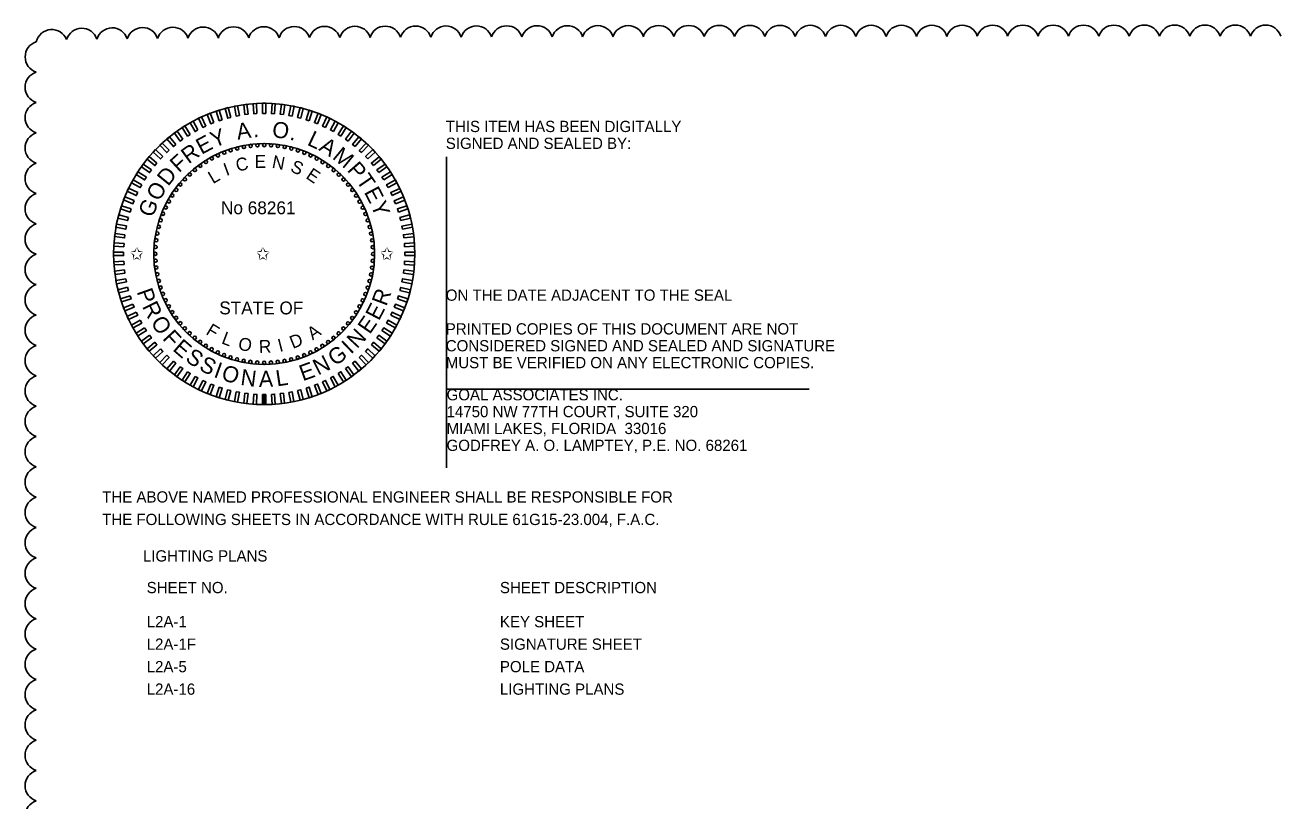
# Model space of a CAD drawing. Extents: x -811 to -790, y -2284 to -2178.
# Drawn here: x -810.98 to -803.16, y -2265.38 to -2260.55 of the extents above; entities that cross this region are included whole.
import ezdxf

# ---------------------------------------------------------------- set-up
doc = ezdxf.new("R2010")
doc.units = 0
for name, color, linetype in [('AdhocPoint_dp', 7, 'Continuous'), ('PlotBorder_dp', 7, 'Continuous'), ('ScratchEle_dp', 7, 'Continuous'), ('TextMinor', 7, 'Continuous'), ('TextMisc', 7, 'Continuous'), ('TextShtNo', 7, 'Continuous')]:
    doc.layers.add(name, color=color, linetype=linetype)

msp = doc.modelspace()

# ---------------------------------------------------------------- linework, layer by layer
at = {"layer": 'AdhocPoint_dp'}
for p, q in [((-808.3546, -2261.3703), (-808.3546, -2263.305)), ((-808.3546, -2262.815), (-806.0979, -2262.815))]:
    msp.add_line(p, q, dxfattribs=at)
at = {"layer": 'ScratchEle_dp'}
for centre, radius, start, end in [((-809.1139, -2260.6566), 0.0991, 17.73544, 162.73544), ((-808.9249, -2260.6558), 0.0991, 17.7132, 162.7132), ((-808.736, -2260.6551), 0.0991, 17.69393, 162.69393), ((-808.547, -2260.6545), 0.0991, 17.67702, 162.67702), ((-808.358, -2260.654), 0.0991, 17.66204, 162.66204), ((-808.169, -2260.6535), 0.0991, 17.64863, 162.64863), ((-807.98, -2260.653), 0.0991, 17.63655, 162.63655), ((-807.791, -2260.6526), 0.0991, 17.62558, 162.62558), ((-807.602, -2260.6522), 0.0991, 17.61556, 162.61556), ((-807.413, -2260.6518), 0.0991, 17.60637, 162.60637), ((-807.224, -2260.6515), 0.0991, 17.5979, 162.5979), ((-807.035, -2260.6512), 0.0991, 17.59006, 162.59006), ((-806.846, -2260.6509), 0.0991, 17.58277, 162.58277), ((-806.657, -2260.6506), 0.0991, 17.57597, 162.57597), ((-806.468, -2260.6504), 0.0991, 17.56961, 162.56961), ((-806.279, -2260.6501), 0.0991, 17.56364, 162.56364), ((-806.09, -2260.6499), 0.0991, 17.55803, 162.55803), ((-805.901, -2260.6498), 0.0991, 17.55274, 162.55274), ((-805.712, -2260.6496), 0.0991, 17.54774, 162.54774), ((-805.523, -2260.6494), 0.0991, 17.54301, 162.54301), ((-805.334, -2260.6493), 0.0991, 17.53852, 162.53852), ((-805.145, -2260.6492), 0.0991, 17.53425, 162.53425), ((-804.956, -2260.6491), 0.0991, 17.53018, 162.53018), ((-804.767, -2260.649), 0.0991, 17.52631, 162.52631), ((-804.578, -2260.6489), 0.0991, 17.52261, 162.52261), ((-804.389, -2260.6488), 0.0991, 17.51907, 162.51907), ((-804.2, -2260.6488), 0.0991, 17.51569, 162.51569), ((-804.011, -2260.6487), 0.0991, 17.51244, 162.51244), ((-803.822, -2260.6487), 0.0991, 17.50933, 162.50933), ((-803.633, -2260.6487), 0.0991, 17.50633, 162.50633), ((-803.444, -2260.6487), 0.0991, 17.50345, 162.50345), ((-803.2551, -2260.6487), 0.0991, 17.50077, 162.50077), ((-810.8128, -2260.6762), 0.0992, 21.52097, 166.52097), ((-810.6255, -2260.6681), 0.0991, 18.44241, 163.44241), ((-810.4367, -2260.6654), 0.0991, 18.17187, 163.17187), ((-810.2478, -2260.6635), 0.0991, 18.03188, 163.03188), ((-810.0588, -2260.6618), 0.0991, 17.94243, 162.94243), ((-809.8699, -2260.6605), 0.0991, 17.8789, 162.8789), ((-809.6809, -2260.6593), 0.0991, 17.83076, 162.83076), ((-809.4919, -2260.6583), 0.0991, 17.79266, 162.79266), ((-809.3029, -2260.6574), 0.0991, 17.76151, 162.76151), ((-810.8794, -2260.7476), 0.099, 107.5, 252.5), ((-810.8794, -2260.9365), 0.0991, 107.5, 252.5), ((-810.8794, -2261.1255), 0.0991, 107.5, 252.5), ((-810.8794, -2261.3145), 0.0991, 107.5, 252.5), ((-810.8794, -2261.5035), 0.0991, 107.5, 252.5), ((-810.8794, -2261.6925), 0.0991, 107.5, 252.5), ((-810.8794, -2261.8815), 0.0991, 107.5, 252.5), ((-810.8794, -2262.0705), 0.0991, 107.5, 252.5), ((-810.8794, -2262.2595), 0.0991, 107.5, 252.5), ((-810.8794, -2262.4485), 0.0991, 107.5, 252.5), ((-810.8794, -2262.6375), 0.0991, 107.5, 252.5), ((-810.8794, -2262.8265), 0.0991, 107.5, 252.5), ((-810.8794, -2263.0155), 0.0991, 107.5, 252.5), ((-810.8794, -2263.2045), 0.0991, 107.5, 252.5), ((-810.8794, -2263.3935), 0.0991, 107.5, 252.5), ((-810.8794, -2263.5825), 0.0991, 107.5, 252.5), ((-810.8794, -2263.7715), 0.0991, 107.5, 252.5), ((-810.8794, -2263.9605), 0.0991, 107.5, 252.5), ((-810.8794, -2264.1495), 0.0991, 107.5, 252.5), ((-810.8794, -2264.3385), 0.0991, 107.5, 252.5), ((-810.8794, -2264.5275), 0.0991, 107.5, 252.5), ((-810.8794, -2264.7165), 0.0991, 107.5, 252.5), ((-810.8794, -2264.9055), 0.0991, 107.5, 252.5), ((-810.8794, -2265.0945), 0.0991, 107.5, 252.5), ((-810.8794, -2265.2835), 0.0991, 107.50047, 252.50047), ((-810.8794, -2265.4725), 0.0991, 107.52584, 252.52584)]:
    msp.add_arc(centre, radius, start, end, dxfattribs=at)
at = {"layer": 'TextMinor'}
for radius in [0.9375, 0.6875]:
    msp.add_circle((-809.4901, -2261.9737), radius, dxfattribs=at)
at = {"layer": 'TextShtNo'}
for p, q in [((-809.5001, -2262.9113), (-809.5003, -2262.8488)), ((-809.4901, -2262.9112), (-809.4903, -2262.8487)), ((-809.4801, -2262.9112), (-809.4803, -2262.8487))]:
    msp.add_line(p, q, dxfattribs=at)
for points in [[(-809.8028, -2261.1564), (-809.8215, -2261.1638), (-809.8445, -2261.1058), (-809.8258, -2261.0983)], [(-809.7508, -2261.1384), (-809.77, -2261.1446), (-809.7893, -2261.0852), (-809.7701, -2261.079)], [(-809.6979, -2261.1237), (-809.7174, -2261.1287), (-809.7329, -2261.0682), (-809.7134, -2261.0632)], [(-809.6441, -2261.1123), (-809.6639, -2261.1161), (-809.6756, -2261.0547), (-809.6558, -2261.051)], [(-809.5897, -2261.1043), (-809.6097, -2261.1069), (-809.6175, -2261.0449), (-809.5975, -2261.0424)], [(-809.5349, -2261.0998), (-809.555, -2261.1011), (-809.559, -2261.0387), (-809.5388, -2261.0375)], [(-809.4799, -2261.0987), (-809.5001, -2261.0987), (-809.5001, -2261.0363), (-809.4799, -2261.0363)], [(-809.425, -2261.1011), (-809.4452, -2261.0998), (-809.4412, -2261.0375), (-809.4211, -2261.0387)], [(-809.3703, -2261.1069), (-809.3904, -2261.1043), (-809.3825, -2261.0424), (-809.3625, -2261.0449)], [(-809.3161, -2261.1161), (-809.336, -2261.1123), (-809.3243, -2261.051), (-809.3044, -2261.0548)], [(-809.2626, -2261.1287), (-809.2822, -2261.1237), (-809.2667, -2261.0632), (-809.2471, -2261.0682)], [(-809.21, -2261.1447), (-809.2292, -2261.1384), (-809.2099, -2261.0791), (-809.1907, -2261.0853)], [(-809.1585, -2261.1639), (-809.1773, -2261.1565), (-809.1543, -2261.0984), (-809.1355, -2261.1058)], [(-809.9504, -2261.2295), (-809.9674, -2261.2403), (-810.0009, -2261.1876), (-809.9838, -2261.1767)], [(-809.9027, -2261.202), (-809.9204, -2261.2118), (-809.9505, -2261.157), (-809.9328, -2261.1473)], [(-809.8535, -2261.1776), (-809.8717, -2261.1862), (-809.8983, -2261.1297), (-809.8801, -2261.1211)], [(-809.1083, -2261.1863), (-809.1266, -2261.1777), (-809.1, -2261.1212), (-809.0817, -2261.1298)], [(-809.0596, -2261.2118), (-809.0773, -2261.2021), (-809.0473, -2261.1474), (-809.0296, -2261.1571)], [(-809.0127, -2261.2404), (-809.0297, -2261.2296), (-808.9962, -2261.1768), (-808.9792, -2261.1877)], [(-810.04, -2261.293), (-810.0556, -2261.3059), (-810.0954, -2261.2578), (-810.0798, -2261.2449)], [(-809.9962, -2261.2598), (-810.0125, -2261.2717), (-810.0492, -2261.2212), (-810.0329, -2261.2093)], [(-808.9675, -2261.2718), (-808.9839, -2261.2599), (-808.9472, -2261.2094), (-808.9308, -2261.2213)], [(-808.9245, -2261.306), (-808.9401, -2261.2931), (-808.9003, -2261.245), (-808.8847, -2261.2579)], [(-810.121, -2261.3673), (-810.1348, -2261.382), (-810.1803, -2261.3393), (-810.1665, -2261.3246)], [(-810.0817, -2261.3289), (-810.0964, -2261.3427), (-810.1391, -2261.2972), (-810.1244, -2261.2834)], [(-808.8837, -2261.3428), (-808.8984, -2261.329), (-808.8557, -2261.2835), (-808.8409, -2261.2973)], [(-808.8453, -2261.3822), (-808.8591, -2261.3674), (-808.8136, -2261.3247), (-808.7998, -2261.3394)], [(-810.192, -2261.4512), (-810.2039, -2261.4675), (-810.2544, -2261.4308), (-810.2426, -2261.4145)], [(-810.1578, -2261.4081), (-810.1707, -2261.4237), (-810.2188, -2261.3839), (-810.206, -2261.3683)], [(-808.8094, -2261.4238), (-808.8223, -2261.4083), (-808.7742, -2261.3685), (-808.7613, -2261.384)], [(-808.7762, -2261.4676), (-808.7881, -2261.4513), (-808.7376, -2261.4146), (-808.7257, -2261.4309)], [(-810.2235, -2261.4963), (-810.2343, -2261.5133), (-810.287, -2261.4798), (-810.2762, -2261.4628)], [(-808.7458, -2261.5135), (-808.7567, -2261.4964), (-808.7039, -2261.463), (-808.6931, -2261.48)], [(-810.2775, -2261.5919), (-810.2861, -2261.6102), (-810.3426, -2261.5836), (-810.334, -2261.5654)], [(-810.252, -2261.5433), (-810.2617, -2261.5609), (-810.3164, -2261.5309), (-810.3067, -2261.5132)], [(-808.7184, -2261.5611), (-808.7281, -2261.5434), (-808.6734, -2261.5133), (-808.6637, -2261.531)], [(-808.694, -2261.6104), (-808.7026, -2261.5921), (-808.6461, -2261.5655), (-808.6375, -2261.5838)], [(-810.3, -2261.6421), (-810.3074, -2261.6609), (-810.3654, -2261.6379), (-810.358, -2261.6192)], [(-808.6728, -2261.6611), (-808.6802, -2261.6423), (-808.6222, -2261.6193), (-808.6147, -2261.6381)], [(-810.3351, -2261.7463), (-810.3401, -2261.7658), (-810.4006, -2261.7503), (-810.3956, -2261.7307)], [(-810.3192, -2261.6936), (-810.3254, -2261.7128), (-810.3848, -2261.6935), (-810.3786, -2261.6743)], [(-808.6548, -2261.713), (-808.661, -2261.6938), (-808.6016, -2261.6745), (-808.5954, -2261.6937)], [(-808.64, -2261.766), (-808.6451, -2261.7464), (-808.5846, -2261.7309), (-808.5796, -2261.7505)], [(-810.3477, -2261.7998), (-810.3515, -2261.8196), (-810.4129, -2261.8079), (-810.4091, -2261.7881)], [(-808.6287, -2261.8198), (-808.6325, -2261.7999), (-808.5711, -2261.7882), (-808.5673, -2261.8081)], [(-810.357, -2261.854), (-810.3595, -2261.874), (-810.4214, -2261.8662), (-810.4189, -2261.8461)], [(-808.6207, -2261.8742), (-808.6232, -2261.8541), (-808.5613, -2261.8463), (-808.5588, -2261.8663)], [(-810.3651, -2261.9635), (-810.3651, -2261.9837), (-810.4276, -2261.9837), (-810.4276, -2261.9635)], [(-810.3628, -2261.9086), (-810.364, -2261.9288), (-810.4264, -2261.9248), (-810.4251, -2261.9047)], [(-808.6162, -2261.929), (-808.6174, -2261.9088), (-808.5551, -2261.9049), (-808.5539, -2261.925)], [(-808.6151, -2261.9839), (-808.6151, -2261.9637), (-808.5526, -2261.9637), (-808.5526, -2261.9839)], [(-810.3641, -2262.0185), (-810.3628, -2262.0387), (-810.4251, -2262.0426), (-810.4264, -2262.0224)], [(-808.6175, -2262.0388), (-808.6162, -2262.0187), (-808.5539, -2262.0226), (-808.5551, -2262.0428)], [(-810.3595, -2262.0733), (-810.357, -2262.0933), (-810.4189, -2262.1011), (-810.4215, -2262.0811)], [(-808.6233, -2262.0935), (-808.6207, -2262.0735), (-808.5588, -2262.0813), (-808.5613, -2262.1013)], [(-810.3516, -2262.1277), (-810.3478, -2262.1475), (-810.4091, -2262.1592), (-810.4129, -2262.1394)], [(-810.3402, -2262.1815), (-810.3352, -2262.201), (-810.3956, -2262.2166), (-810.4007, -2262.197)], [(-808.6451, -2262.2012), (-808.6401, -2262.1817), (-808.5796, -2262.1972), (-808.5846, -2262.2167)], [(-808.6325, -2262.1477), (-808.6287, -2262.1279), (-808.5674, -2262.1396), (-808.5712, -2262.1594)], [(-810.3255, -2262.2344), (-810.3192, -2262.2536), (-810.3786, -2262.2729), (-810.3849, -2262.2537)], [(-808.6611, -2262.2538), (-808.6548, -2262.2346), (-808.5954, -2262.2539), (-808.6017, -2262.2731)], [(-810.3074, -2262.2864), (-810.3, -2262.3051), (-810.3581, -2262.3281), (-810.3655, -2262.3094)], [(-810.2862, -2262.3371), (-810.2776, -2262.3553), (-810.3341, -2262.3819), (-810.3427, -2262.3637)], [(-808.7027, -2262.3555), (-808.6941, -2262.3372), (-808.6376, -2262.3638), (-808.6462, -2262.3821)], [(-808.6803, -2262.3053), (-808.6729, -2262.2866), (-808.6148, -2262.3095), (-808.6222, -2262.3283)], [(-810.2618, -2262.3864), (-810.2521, -2262.404), (-810.3068, -2262.4341), (-810.3165, -2262.4164)], [(-810.2344, -2262.434), (-810.2236, -2262.451), (-810.2763, -2262.4845), (-810.2871, -2262.4674)], [(-808.7568, -2262.4512), (-808.7459, -2262.4341), (-808.6932, -2262.4676), (-808.704, -2262.4847)], [(-808.7282, -2262.4042), (-808.7185, -2262.3865), (-808.6638, -2262.4166), (-808.6735, -2262.4343)], [(-810.204, -2262.4798), (-810.1922, -2262.4961), (-810.2427, -2262.5328), (-810.2545, -2262.5165)], [(-808.7882, -2262.4963), (-808.7763, -2262.48), (-808.7258, -2262.5167), (-808.7377, -2262.533)], [(-810.1708, -2262.5236), (-810.158, -2262.5392), (-810.2061, -2262.579), (-810.2189, -2262.5634)], [(-810.135, -2262.5653), (-810.1211, -2262.58), (-810.1667, -2262.6228), (-810.1805, -2262.608)], [(-808.8592, -2262.5802), (-808.8454, -2262.5654), (-808.7999, -2262.6082), (-808.8137, -2262.6229)], [(-808.8224, -2262.5393), (-808.8095, -2262.5238), (-808.7614, -2262.5636), (-808.7743, -2262.5791)], [(-810.0965, -2262.6046), (-810.0818, -2262.6184), (-810.1246, -2262.664), (-810.1393, -2262.6501)], [(-810.0557, -2262.6415), (-810.0402, -2262.6543), (-810.08, -2262.7024), (-810.0955, -2262.6896)], [(-808.9402, -2262.6544), (-808.9246, -2262.6416), (-808.8848, -2262.6897), (-808.9004, -2262.7026)], [(-808.8985, -2262.6186), (-808.8838, -2262.6048), (-808.8411, -2262.6503), (-808.8558, -2262.6641)], [(-810.0127, -2262.6757), (-809.9964, -2262.6875), (-810.0331, -2262.738), (-810.0494, -2262.7262)], [(-809.9676, -2262.7071), (-809.9505, -2262.7179), (-809.984, -2262.7706), (-810.001, -2262.7598)], [(-809.9206, -2262.7356), (-809.9029, -2262.7453), (-809.933, -2262.8001), (-809.9507, -2262.7903)], [(-809.0775, -2262.7454), (-809.0598, -2262.7357), (-809.0297, -2262.7904), (-809.0474, -2262.8001)], [(-809.0299, -2262.718), (-809.0128, -2262.7072), (-808.9794, -2262.7599), (-808.9964, -2262.7707)], [(-808.984, -2262.6876), (-808.9677, -2262.6758), (-808.931, -2262.7263), (-808.9473, -2262.7381)], [(-809.8719, -2262.7611), (-809.8536, -2262.7697), (-809.8802, -2262.8262), (-809.8985, -2262.8176)], [(-809.8217, -2262.7836), (-809.8029, -2262.791), (-809.8259, -2262.849), (-809.8447, -2262.8416)], [(-809.7702, -2262.8028), (-809.751, -2262.809), (-809.7703, -2262.8684), (-809.7895, -2262.8622)], [(-809.7176, -2262.8187), (-809.698, -2262.8238), (-809.7136, -2262.8842), (-809.7331, -2262.8792)], [(-809.2824, -2262.8238), (-809.2628, -2262.8188), (-809.2473, -2262.8793), (-809.2668, -2262.8843)], [(-809.2294, -2262.8091), (-809.2102, -2262.8028), (-809.1909, -2262.8622), (-809.2101, -2262.8685)], [(-809.1775, -2262.7911), (-809.1587, -2262.7836), (-809.1357, -2262.8417), (-809.1545, -2262.8491)], [(-809.1268, -2262.7698), (-809.1085, -2262.7612), (-809.0819, -2262.8177), (-809.1002, -2262.8263)], [(-809.6641, -2262.8314), (-809.6443, -2262.8351), (-809.656, -2262.8965), (-809.6758, -2262.8927)], [(-809.6099, -2262.8406), (-809.5899, -2262.8431), (-809.5977, -2262.9051), (-809.6177, -2262.9025)], [(-809.5552, -2262.8464), (-809.5351, -2262.8477), (-809.539, -2262.91), (-809.5591, -2262.9087)], [(-809.5003, -2262.8488), (-809.4801, -2262.8488), (-809.4801, -2262.9112), (-809.5003, -2262.9112)], [(-809.4453, -2262.8477), (-809.4252, -2262.8464), (-809.4213, -2262.9087), (-809.4414, -2262.91)], [(-809.3906, -2262.8431), (-809.3705, -2262.8406), (-809.3627, -2262.9026), (-809.3827, -2262.9051)], [(-809.3362, -2262.8352), (-809.3163, -2262.8314), (-809.3046, -2262.8927), (-809.3245, -2262.8965)]]:
    msp.add_lwpolyline(points, close=True, dxfattribs=at)
for centre in [(-809.739, -2261.3436), (-809.6989, -2261.3292), (-809.6581, -2261.3174), (-809.6165, -2261.3082), (-809.5745, -2261.3015), (-809.5321, -2261.2976), (-809.4896, -2261.2963), (-809.447, -2261.2976), (-809.4046, -2261.3017), (-809.3626, -2261.3084), (-809.3211, -2261.3177), (-809.2802, -2261.3296), (-809.2402, -2261.344), (-809.8879, -2261.4253), (-809.8526, -2261.4014), (-809.816, -2261.3798), (-809.7781, -2261.3605), (-809.2012, -2261.361), (-809.1633, -2261.3803), (-809.1266, -2261.402), (-809.0915, -2261.426), (-809.9535, -2261.4795), (-809.9215, -2261.4514), (-809.0578, -2261.4521), (-809.0259, -2261.4803), (-810.0379, -2261.5751), (-810.0118, -2261.5415), (-809.9836, -2261.5096), (-808.9959, -2261.5104), (-808.9678, -2261.5423), (-808.9417, -2261.576), (-810.0835, -2261.6469), (-810.0618, -2261.6102), (-808.9178, -2261.6112), (-808.8962, -2261.6478), (-810.1198, -2261.7238), (-810.1029, -2261.6848), (-808.8769, -2261.6858), (-808.86, -2261.7249), (-810.1462, -2261.8047), (-810.1343, -2261.7638), (-808.8456, -2261.7649), (-808.8338, -2261.8058), (-810.1622, -2261.8883), (-810.1555, -2261.8462), (-808.8245, -2261.8473), (-808.8179, -2261.8894), (-810.1676, -2261.9732), (-810.1662, -2261.9306), (-808.814, -2261.9318), (-808.8126, -2261.9743), (-810.1663, -2262.0157), (-808.814, -2262.0168), (-810.1623, -2262.0581), (-810.1557, -2262.1001), (-808.8248, -2262.1012), (-808.8181, -2262.0592), (-810.1464, -2262.1417), (-810.1346, -2262.1825), (-808.846, -2262.1836), (-808.8341, -2262.1428), (-810.1202, -2262.2226), (-810.1033, -2262.2617), (-808.8774, -2262.2627), (-808.8604, -2262.2236), (-810.0841, -2262.2996), (-810.0624, -2262.3363), (-808.9184, -2262.3372), (-808.8967, -2262.3006), (-810.0385, -2262.3715), (-810.0125, -2262.4051), (-809.9844, -2262.4371), (-808.9967, -2262.4379), (-808.9685, -2262.406), (-808.9424, -2262.3724), (-809.9543, -2262.4672), (-809.9224, -2262.4954), (-809.8888, -2262.5215), (-809.0924, -2262.5221), (-809.0587, -2262.4961), (-809.0268, -2262.468), (-809.8536, -2262.5454), (-809.817, -2262.5671), (-809.7791, -2262.5865), (-809.2022, -2262.587), (-809.1642, -2262.5677), (-809.1276, -2262.546), (-809.74, -2262.6034), (-809.7, -2262.6179), (-809.6591, -2262.6298), (-809.6176, -2262.6391), (-809.5756, -2262.6458), (-809.5332, -2262.6498), (-809.4901, -2262.6512), (-809.4481, -2262.6499), (-809.4058, -2262.6459), (-809.3637, -2262.6393), (-809.3222, -2262.6301), (-809.2813, -2262.6182), (-809.2412, -2262.6038)]:
    msp.add_circle(centre, 0.01, dxfattribs=at)

# ---------------------------------------------------------------- texts
at = {"layer": 'PlotBorder_dp'}
for s, p in [('THIS ITEM HAS BEEN DIGITALLY', (-808.3596, -2261.2152)), ('SIGNED AND SEALED BY:', (-808.3596, -2261.3202)), ('ON THE DATE ADJACENT TO THE SEAL', (-808.3596, -2262.2652)), ('PRINTED COPIES OF THIS DOCUMENT ARE NOT ', (-808.3596, -2262.4752)), ('CONSIDERED SIGNED AND SEALED AND SIGNATURE ', (-808.3596, -2262.5802)), ('MUST BE VERIFIED ON ANY ELECTRONIC COPIES.', (-808.3596, -2262.6852)), ('GOAL ASSOCIATES INC.', (-808.3546, -2262.885)), ('14750 NW 77TH COURT, SUITE 320', (-808.3546, -2262.99)), ('MIAMI LAKES, FLORIDA  33016', (-808.3546, -2263.095)), ('GODFREY A. O. LAMPTEY, P.E. NO. 68261', (-808.3546, -2263.2)), ('THE ABOVE NAMED PROFESSIONAL ENGINEER SHALL BE RESPONSIBLE FOR ', (-810.4987, -2263.5212)), ('THE FOLLOWING SHEETS IN ACCORDANCE WITH RULE 61G15-23.004, F.A.C.', (-810.4987, -2263.6612)), ('LIGHTING PLANS', (-810.245, -2263.8882))]:
    msp.add_text(s, height=0.07, dxfattribs=at).set_placement(p)
at = {"layer": 'TextMisc'}
for s, p in [('SHEET NO.', (-810.2215, -2264.0852)), ('SHEET DESCRIPTION', (-808.0226, -2264.0852)), ('L2A-1', (-810.2215, -2264.2974)), ('KEY SHEET', (-808.0226, -2264.2974)), ('L2A-1F', (-810.2215, -2264.4374)), ('SIGNATURE SHEET', (-808.0226, -2264.4374)), ('L2A-5', (-810.2215, -2264.5774)), ('POLE DATA', (-808.0226, -2264.5774)), ('L2A-16', (-810.2215, -2264.7174)), ('LIGHTING PLANS', (-808.0226, -2264.7174))]:
    msp.add_text(s, height=0.07, dxfattribs=at).set_placement(p)
at = {"layer": 'TextShtNo'}
for s, height, rotation, p in [('A', 0.1, 8.80884, (-809.6551, -2261.2631)), ('O', 0.1, 352.18771, (-809.4449, -2261.2456)), ('E', 0.1, 28.10553, (-809.8806, -2261.3575)), ('Y', 0.1, 21.06329, (-809.8021, -2261.3143)), ('.', 0.1, 1.04184, (-809.5575, -2261.2473)), ('.', 0.1, 343.52684, (-809.3358, -2261.2607)), ('L', 0.1, 334.67271, (-809.2279, -2261.293)), ('A', 0.1, 328.40959, (-809.1552, -2261.3257)), ('R', 0.1, 35.92688, (-809.9609, -2261.4164)), ('M', 0.1, 320.6426, (-809.0707, -2261.3769)), ('F', 0.1, 42.37723, (-810.0205, -2261.4728)), ('I', 0.08, 20.01168, (-809.7258, -2261.4897)), ('C', 0.08, 12.20255, (-809.6579, -2261.4621)), ('E', 0.08, 0.41861, (-809.5498, -2261.4386)), ('N', 0.08, 349.29143, (-809.4455, -2261.4372)), ('S', 0.08, 337.02207, (-809.3325, -2261.4589)), ('P', 0.1, 311.19658, (-808.9784, -2261.4538)), ('D', 0.1, 50.8569, (-810.0885, -2261.5565)), ('L', 0.08, 30.40215, (-809.8093, -2261.5401)), ('E', 0.08, 325.86633, (-809.2358, -2261.4992)), ('T', 0.1, 304.45632, (-808.9209, -2261.5175)), ('O', 0.1, 59.51777, (-810.1446, -2261.6514)), ('E', 0.1, 297.63152, (-808.8707, -2261.5883)), ('G', 0.1, 68.0518, (-810.1851, -2261.7521)), ('Y', 0.1, 290.58928, (-808.8281, -2261.6672)), ('P', 0.1, 289.40551, (-810.2848, -2262.2083)), ('R', 0.1, 69.5134, (-808.7299, -2262.3034)), ('R', 0.1, 296.14576, (-810.2518, -2262.3)), ('E', 0.1, 62.47116, (-808.7761, -2262.3941)), ('E', 0.1, 55.42892, (-808.833, -2262.4785)), ('O', 0.1, 303.96711, (-810.2003, -2262.4006)), ('F', 0.08, 328.72408, (-809.8582, -2262.4703)), ('A', 0.08, 34.49917, (-809.1883, -2262.5131)), ('F', 0.1, 312.62798, (-810.1279, -2262.5027)), ('E', 0.1, 319.07833, (-810.0645, -2262.571)), ('L', 0.08, 339.29159, (-809.7609, -2262.5294)), ('O', 0.08, 349.68206, (-809.6562, -2262.5691)), ('R', 0.08, 2.33977, (-809.5217, -2262.591)), ('I', 0.08, 14.20366, (-809.3941, -2262.5843)), ('D', 0.08, 22.01279, (-809.312, -2262.5656)), ('I', 0.1, 43.64556, (-808.9499, -2262.6021)), ('N', 0.1, 47.17876, (-808.9123, -2262.5676)), ('S', 0.1, 326.12056, (-809.9869, -2262.6369)), ('G', 0.1, 35.11153, (-809.0492, -2262.6753)), ('S', 0.1, 333.193, (-809.9015, -2262.693)), ('I', 0.1, 340.26543, (-809.8098, -2262.7382)), ('O', 0.1, 343.79863, (-809.7621, -2262.7564)), ('E', 0.1, 19.81912, (-809.2498, -2262.7667)), ('N', 0.1, 26.86136, (-809.1544, -2262.7313)), ('N', 0.1, 352.45949, (-809.6411, -2262.7885)), ('A', 0.1, 0.70966, (-809.5227, -2262.8017)), ('L', 0.1, 8.47665, (-809.4105, -2262.7985))]:
    msp.add_text(s, height=height, rotation=rotation, dxfattribs=at).set_placement(p)
for s, p in [('No 68261', (-809.7591, -2261.7265)), ('✩', (-810.3251, -2262.0117)), ('✩', (-809.5404, -2262.0117)), ('✩', (-808.7685, -2262.0117)), ('STATE OF', (-809.7698, -2262.3499))]:
    msp.add_text(s, height=0.08, dxfattribs=at).set_placement(p)

doc.saveas('drawing.dxf')
